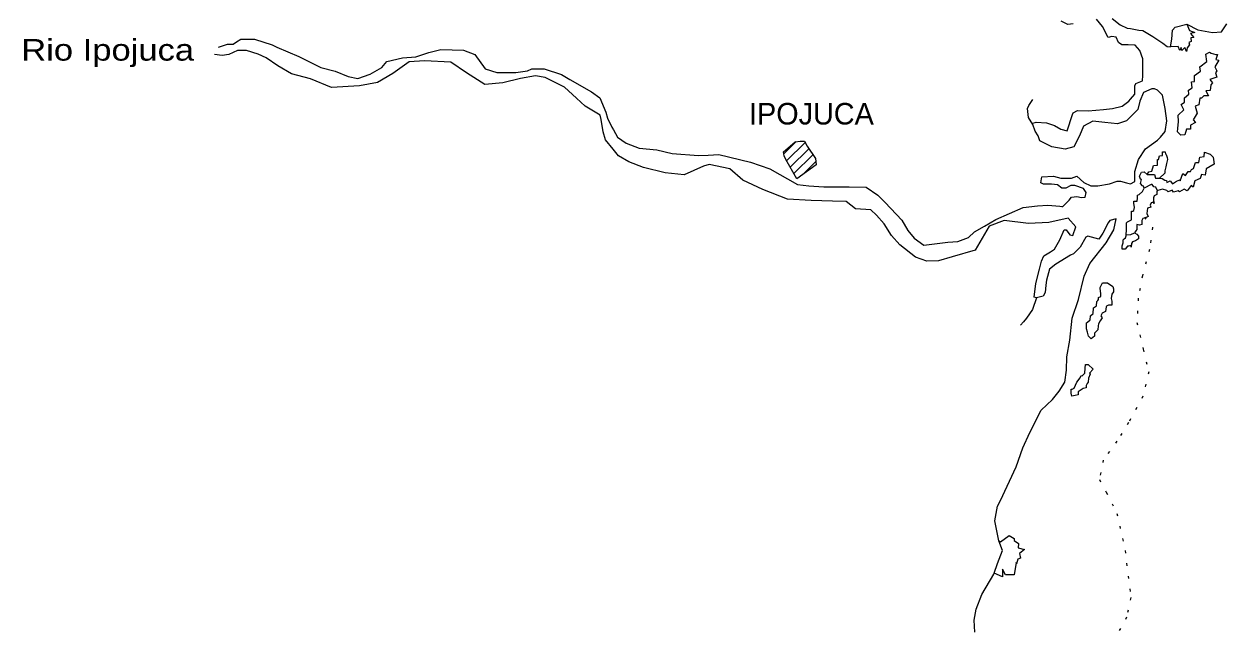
# Model space of a CAD drawing. Extents: x 47169 to 972804, y 7447977 to 9608469.
# Drawn here: x 909327 to 947160, y 9054600 to 9073613 of the extents above; entities that cross this region are included whole.
import ezdxf
from ezdxf.enums import TextEntityAlignment as Align

# ---------------------------------------------------------------- set-up
doc = ezdxf.new("R2010")
doc.units = 0
doc.header["$LTSCALE"] = 270
doc.linetypes.add('DOTTED', pattern=[1.5, 0.3, -1.2])
doc.layers.add('1', color=7, linetype='Continuous', lineweight=13)
doc.layers.add('3', color=7, linetype='Continuous')

msp = doc.modelspace()

# ---------------------------------------------------------------- linework, layer by layer
at = {"layer": '1'}
for p, q in [((933223.9, 9069536.3), (933612.8, 9069919.2)), ((933311, 9069311.6), (933895, 9069886.4)), ((933422.6, 9069111), (934012.3, 9069691.3)), ((933534.3, 9068911.5), (934138.4, 9069505)), ((933824.3, 9068886.4), (934232.2, 9069287.9))]:
    msp.add_line(p, q, dxfattribs=at)
for points in [[(941002.4, 9070544.8), (941018.4, 9070488.1), (941162.3, 9070528.7), (941488.8, 9070512.1), (941736.3, 9070423.1), (941934.9, 9070310.2), (942134.1, 9070261.7), (942303.8, 9070767.5), (942319.8, 9070822.8), (942462.9, 9070895.6), (942790.6, 9070886.7), (943276.7, 9070926), (943556.2, 9070957.5), (943859.5, 9071037.5), (944075.2, 9071189.3), (944131, 9071253.1), (944267.3, 9071413.5), (944267.2, 9071509.9), (944267.7, 9071670.6), (944299.4, 9071742.3), (944507.8, 9071831.1), (944516.1, 9071999.4), (944516.1, 9072103.6), (944509.3, 9072521.5), (944421.6, 9072786.2), (944270.9, 9072947.3), (944054.7, 9072964), (943856, 9072963.8), (943751.9, 9073036.9), (943673, 9073197.3), (943537.5, 9073222), (943425.7, 9073189.8), (943250.4, 9073535.2), (943059.6, 9073768.8)], [(942325.2, 9073625.6), (942158.3, 9073601.8), (941950.8, 9073705.9)], [(943554.3, 9073791.5), (943801.8, 9073590.5), (944024.8, 9073485.2), (944128.3, 9073469.7), (944391.7, 9073420.5), (944518.5, 9073412.5), (944830, 9073218.7), (945147.9, 9073009.3), (945275, 9072912.6), (945387.4, 9072897.1), (945427.4, 9073137.2), (945452.4, 9073418.4), (945531.7, 9073515.2), (945899.2, 9073610), (946241.8, 9073433.6), (946704.5, 9073352.3), (946991.7, 9073367.1), (947159.8, 9073615.9)], [(945899.2, 9073610), (945986.5, 9073409.6), (946145.9, 9073344.8), (946018.7, 9073312.9), (946113.4, 9073192.2), (946026.2, 9073184.2), (946033.8, 9073064.4), (945961.7, 9073031.9), (945985.2, 9072959.6), (945905.9, 9072864), (945889.2, 9072751.2), (945834.3, 9072880.3), (945746.1, 9072783.7), (945721.6, 9072872.6), (945682.1, 9072784.3), (945627, 9072904.6), (945387.4, 9072897.1)], [(928346, 9069286.9), (928021.2, 9069466.3), (927855.6, 9069684.1), (927610.2, 9069974.6), (927540.9, 9070223.5), (927473, 9070608.7), (927442.3, 9070745.3), (926974, 9071030.3), (926703.9, 9071281.2), (926324.4, 9071629.5), (925720.4, 9071932.5), (925408.6, 9071984.3), (924936.6, 9071901.4), (924384.7, 9071770.5), (923816.9, 9071712.9), (923237.8, 9072079.8), (922745.7, 9072420.3), (921922.8, 9072453.8), (921435.9, 9072426.5), (920921.4, 9072055.8), (920439.8, 9071781.3), (919879.3, 9071667.1), (918992.8, 9071620.3), (918339.9, 9071891.4), (917734.6, 9072050.2), (917313.3, 9072302.4), (916940.6, 9072555.3), (916685.7, 9072669.7), (916327.1, 9072785), (916040.1, 9072781.1), (915767.5, 9072655.2), (915559.8, 9072626.2), (915320.6, 9072651.8)], [(915437.6, 9072888.9), (915724.2, 9072977), (915899.7, 9072976.4), (916004.2, 9073056.3), (916147.3, 9073136.9), (916577.6, 9073136.1), (917127.6, 9072959), (917279.2, 9072886.7), (917972.6, 9072588.6), (918657.9, 9072250.7), (919112.5, 9072137.7), (919519.1, 9071959.8), (919829.7, 9071903.6), (920212.8, 9072039.5), (920580.1, 9072247.5), (920732, 9072432.2), (921234.1, 9072551.4), (921649.3, 9072583.9), (922056.7, 9072719.6), (922439.5, 9072815.6), (923148.8, 9072789.8), (923507.2, 9072653.3), (923826.1, 9072202.6), (924192.5, 9072090.4), (924790.6, 9072089), (925157.5, 9072145.2), (925292.8, 9072209.2), (925684.5, 9072208.7), (926225.7, 9072030.5), (926496.7, 9071869.4), (927173.8, 9071483.7), (927436.7, 9071290.6), (927627.7, 9070848.7), (927675.4, 9070655.5), (927810.5, 9070367.1), (927866, 9070286.8), (927992.8, 9070052.8), (928263.5, 9069868.4), (928670.3, 9069714.8), (929228.1, 9069658.2), (929707, 9069544.9), (930536.2, 9069479), (930847.4, 9069487), (931182.1, 9069510.2), (932178.3, 9069267.6), (932784.3, 9069057.6), (933652.3, 9068574.6), (934011.6, 9068526.6), (934481.3, 9068493.1), (934633.6, 9068492.6), (934888.6, 9068492.3), (935279.2, 9068491.7), (935813.2, 9068483), (936180.4, 9068233.2), (936411, 9068008.1), (936936.1, 9067445.4), (937119.3, 9067123.2), (937317.7, 9066882.9), (937627.8, 9066664.8), (938378.1, 9066760.2), (938697.2, 9066783.6), (939032.8, 9066903.2), (939216.8, 9067087.5), (939535.3, 9067263.8), (939887.3, 9067471.8), (940749.7, 9067847.6), (941203.8, 9067895), (941523, 9067918.4), (941905.6, 9067885.6), (941961.8, 9067877.3), (942001.6, 9067876.9), (942201.2, 9068077.7), (942266.1, 9068173.4), (942440.8, 9068197.1), (942585, 9068164.6), (942696.6, 9068173.4), (942729, 9068317.2), (942648.6, 9068445.4), (942378, 9068534.7), (942250, 9068534.9), (942090.2, 9068455.6), (941963.3, 9068455.8), (941835.3, 9068560.2), (941636.9, 9068584.4), (941389.7, 9068584.7), (941301.8, 9068625.5), (941333.5, 9068810.2), (941701.2, 9068833.1), (941932.3, 9068768.6), (942155.3, 9068768.6), (942274.5, 9068767.3), (942442.9, 9068832.1), (942657.2, 9068638.2), (942880.1, 9068526.2), (943104.1, 9068525), (943463.5, 9068588.9), (943710.5, 9068677.2), (943814.2, 9068676.2), (943998, 9068627.7), (944124.6, 9068595.4), (944261.1, 9068667.1)], [(944261.1, 9068667.1), (944261, 9068980.8), (944381.9, 9069357.5), (944598.3, 9069686.6), (944973.1, 9069966.5), (945070.1, 9070055.3), (945213.2, 9070240), (945270.7, 9070568.6), (945215.2, 9070962.6), (945129, 9071380.2), (944977.2, 9071540.3), (944881.5, 9071573.4), (944794.4, 9071581), (944538.2, 9071461.7), (944418.4, 9071188), (944353.9, 9070923.8), (944001.5, 9070570.6), (943714.6, 9070474.9), (943323.2, 9070516.6), (942940.7, 9070557.1), (942653.2, 9070404.8), (942525.4, 9070100.3), (942348.6, 9069755.2), (942069.7, 9069676), (941655.4, 9069749), (941279.9, 9069942.3), (941217.6, 9070102.6), (941129.6, 9070247.5), (941057.8, 9070456.6), (941002.4, 9070544.8), (940923.2, 9070673), (940891.9, 9070962.6), (940931.5, 9071058.6), (941051.5, 9071243.6)], [(944651.8, 9068883.7), (944707.9, 9068971.8), (944796.4, 9068987.5), (944852.3, 9069164.2), (944971.7, 9069179.6), (944980.1, 9069356.8), (945012.1, 9069356.5), (945036.4, 9069469.3), (945132.6, 9069485), (945132.7, 9069596.9), (945219.9, 9069597.1), (945228, 9069532.7), (945252.1, 9069509.2), (945283.2, 9069420.2), (945291.3, 9069355.9), (945259.2, 9069235.4), (945242.6, 9069123.6), (945210.3, 9068995.4), (945203.1, 9068931.2), (945034.8, 9068770)], [(939229.8, 9054502), (939209.4, 9054871.2), (939269.3, 9055221.9), (939449.5, 9055684.4), (939823.5, 9056321.1), (939839.2, 9056353.1), (939938.4, 9056655.8), (940102.6, 9057069.7), (939985.4, 9057367.9), (939863.9, 9057993.1), (939940.4, 9058456.7), (940038.3, 9058639.6), (940528, 9059690.8), (940741.7, 9060297), (940961.8, 9060774.6), (941312.2, 9061474.8), (941675.4, 9061814.6), (941885.6, 9062076.2), (942056.2, 9062354.8), (942115.3, 9062738.8), (942119.6, 9063154.3), (942221, 9063673.1), (942292.1, 9064369.5), (942489.1, 9064959.3), (942672.2, 9065693.3), (942851.7, 9066091.5), (943361.6, 9066734.7), (943597.6, 9067147.8), (943680.6, 9067491.7), (943480.3, 9067437.2), (943424.4, 9067365.7), (943261, 9067039.3), (943131, 9066849), (942788.7, 9066941.1), (942716.7, 9066909.8), (942545.7, 9066600.1), (942336.1, 9066386.1), (942239.7, 9066347.2), (941773.2, 9066063.8), (941580.8, 9065914), (941488.9, 9065562.5), (941463.1, 9065410.9), (941445.2, 9065179.5), (941380, 9065059.3), (941172, 9065006.1), (941092.8, 9065031.3), (941144.6, 9065455.2), (941260.7, 9065909.5), (941327.3, 9066164.8), (941400.8, 9066332.6), (941609.5, 9066450.1), (941738.4, 9066536.3), (941901.4, 9066830.6), (942040.3, 9067141.7), (942104.4, 9067148.8), (942214.2, 9066988.1), (942317.8, 9066970.4), (942408.9, 9067241), (942171, 9067508.3), (941554.9, 9067371.6), (940915.7, 9067346.1), (940157.4, 9067442.5), (939684.2, 9067256.7), (939238.5, 9066508.7), (938516.9, 9066301.1), (938084, 9066169.2), (937716.4, 9066157.4), (937366.9, 9066289.5), (936867.5, 9066671.4), (936606.8, 9066970), (936378.8, 9067333.5), (936133.2, 9067607.5), (935959.4, 9067770), (935473.1, 9067807.1), (935179.7, 9068035), (934756.1, 9068047), (934077.6, 9068071.6), (933343.1, 9068111.1), (932563.7, 9068415.9), (931935.5, 9068711.5), (931523, 9069060.2), (930869.9, 9069195.3), (930692.9, 9069149.4), (930083.2, 9068875.2), (929493.5, 9068937.6), (928807.7, 9069106.2), (928346, 9069286.9)], [(944986.6, 9068377), (944954.3, 9068353), (944953.3, 9068256.6), (944873.4, 9068216.4), (944849.6, 9068152.3), (944849.8, 9068064.8), (944873.1, 9067968.1), (944841.6, 9068016.1), (944777.3, 9067992.4), (944745.6, 9067919.6), (944761.5, 9067856.2), (944657.5, 9067824.1), (944641.5, 9067663.5), (944681.3, 9067566.7), (944577, 9067511.2), (944512.9, 9067503), (944481.3, 9067439.1), (944481.1, 9067310.5), (944409.1, 9067286.9), (944321.1, 9067311), (944321.7, 9067158.1), (944289.3, 9067117.4), (944256.6, 9067053.5), (944321.2, 9067005.2), (944376.9, 9066949.2), (944376, 9066860.5), (944280.5, 9066797.2), (944184.2, 9066772.7), (944160.4, 9066716.4), (944152.7, 9066604.6), (944136.6, 9066652.4), (944064.6, 9066628.8), (944032.6, 9066629.1), (943961.1, 9066540.1), (943865.1, 9066541), (943865, 9066637.5), (943881.1, 9066701.6), (943897.9, 9066733.5), (943897.8, 9066830), (943930.2, 9066861.8), (943969.1, 9066893.5), (943994.1, 9066957.5), (943993.3, 9066989.7), (944136.8, 9066998.2), (944256.6, 9067053.5)], [(943993.3, 9066989.7), (943993.8, 9067038.5), (944002.1, 9067094.9), (944002.3, 9067223.5), (944002.7, 9067367.5), (944035, 9067399.3), (944154.8, 9067455.7), (944154.9, 9067575.4), (944155.4, 9067728.4), (944202.9, 9067727.9), (944235.1, 9067751.9), (944250.5, 9067848.2), (944235.3, 9067984.7), (944236, 9068049), (944307.7, 9068049.3), (944338.6, 9068049), (944347.3, 9068145.3), (944347.2, 9068234), (944403.7, 9068257.8), (944499.6, 9068354.3), (944555.8, 9068458)], [(941172, 9065006.1), (941045.8, 9064643.9), (940853.2, 9064371), (940757, 9064250.1), (940669.9, 9064146.8)], [(939985.4, 9057367.9), (940032.5, 9057335.3), (940314.9, 9057539.6), (940472.8, 9057441.5), (940472.1, 9057378.4), (940606.8, 9057280.6), (940590, 9057152.2), (940796.9, 9057094.6), (940635.7, 9056975.5), (940666.1, 9056823.3), (940578.6, 9056792.1), (940545.1, 9056648.4), (940529, 9056688.4), (940469.8, 9056305.6), (940198.4, 9056300.6), (940104.2, 9056477.8), (940101.7, 9056237.3), (939839.2, 9056353.1)]]:
    msp.add_lwpolyline(points, dxfattribs=at)
for points in [[(946814.4, 9072660.7), (946863, 9072661.3), (946806.1, 9072500.1), (946901.9, 9072475.8), (946781.6, 9072267.6), (946845.5, 9072147.2), (946805.1, 9072083.4), (946836.8, 9071946.7), (946620.8, 9071866.9), (946709.2, 9071769.6), (946653.2, 9071698.1), (946628.2, 9071521), (946492.4, 9071513.6), (946580.1, 9071353.1), (946428.9, 9071353.5), (946364.2, 9071288.8), (946309, 9071281.6), (946275.9, 9071072.5), (946165.1, 9071032.6), (946228, 9070815.8), (946092.3, 9070606.7), (946172, 9070518.3), (946012.1, 9070430.2), (946012, 9070310.5), (945891.7, 9070310.6), (945835.8, 9070133.8), (945707.6, 9070118.5), (945604.9, 9070222.7), (945620.4, 9070335.6), (945637, 9070551.5), (945629.1, 9070752.2), (945805.2, 9070913.3), (945717.6, 9071089.3), (945829.8, 9071161.3), (945830.1, 9071297.6), (945965.9, 9071410.4), (945950.7, 9071539.1), (946070.7, 9071611), (946047.2, 9071795.2), (946134.5, 9071803.2), (946135.3, 9071996.1), (946326.6, 9072132.6), (946311.4, 9072269.1), (946527.3, 9072436.5), (946495.5, 9072669.6), (946615.4, 9072733.7), (946663.6, 9072701.1)], [(933628.6, 9068743.2), (933287.1, 9069354), (933232.1, 9069475.3), (933215.6, 9069595.1), (933583, 9069916.1), (933735.5, 9069931.2), (933871.2, 9069931), (933957.9, 9069770.5), (934220, 9069384.5), (934244.5, 9069192.5)], [(944555.8, 9068458), (944532.2, 9068514.7), (944500.3, 9068530.6), (944443.7, 9068603.2), (944468.1, 9068723.7), (944444, 9068739.5), (944405.1, 9068827.5), (944469.4, 9068956.5), (944556.7, 9068964.4), (944651.8, 9068883.7), (944883.6, 9068883.5), (944915.6, 9068771.2), (945034.8, 9068770), (945122.9, 9068754.7), (945201.8, 9068706.2), (945258.1, 9068697.9), (945266.2, 9068633.5), (945377.2, 9068690), (945449, 9068592.8), (945576.8, 9068673.5), (945673.3, 9068721.3), (945688.4, 9068689), (945769.1, 9068913.1), (945856.8, 9068856.8), (945944.1, 9068977.8), (946015.9, 9068977.1), (946040.8, 9069041.1), (946104.1, 9069073.7), (946169, 9069265.9), (946272.7, 9069265.9), (946304.2, 9069434.1), (946447.9, 9069450.3), (946457, 9069586.5), (946631.9, 9069521.6), (946727, 9069433), (946758.8, 9069208.8), (946511.2, 9069065.1), (946478.2, 9068863.7), (946359.2, 9068880.4), (946319.3, 9068760), (946150.8, 9068687.5), (946094.7, 9068487.5), (946038.9, 9068535.7), (945911.4, 9068375.2), (945815.9, 9068423.9), (945663.9, 9068343.4), (945624.5, 9068376), (945480.5, 9068327.6), (945440.3, 9068392.3), (945312.9, 9068344.8), (945264.8, 9068384.1), (945137.1, 9068425.3), (944986.6, 9068377), (944970.2, 9068392.7), (944922.6, 9068489.6), (944858.7, 9068498.1), (944810.8, 9068570.6), (944778.8, 9068569.8)], [(943567.1, 9065361.6), (943590.6, 9065289.3), (943591, 9065225), (943590.7, 9065192.8), (943542.6, 9065128), (943519.1, 9064991.9), (943542.4, 9064903), (943542.2, 9064775.5), (943430.8, 9064775.6), (943366.5, 9064750.7), (943366.3, 9064727.5), (943342.6, 9064574.8), (943230.7, 9064527.2), (943197.8, 9064438.8), (943230.2, 9064374.2), (943174.1, 9064286.1), (943117.9, 9064189.2), (943109.5, 9064125), (943093.9, 9063996.6), (942997.9, 9063893.4), (942997, 9063804.7), (942893.4, 9063716), (942806.1, 9063804.5), (942774.3, 9063933.4), (942743.3, 9064030.1), (942743.1, 9064223), (942775.2, 9064238.1), (942855.5, 9064318.2), (942863.5, 9064446.7), (942951.4, 9064518.9), (942967.6, 9064696.1), (943055.3, 9064751.7), (943072.2, 9064887.9), (943095.7, 9064920.9), (943119.2, 9064952.8), (943119.9, 9065017.1), (943191.9, 9065048.5), (943191.8, 9065144.9), (943176.8, 9065298), (943176.1, 9065330.1), (943248.2, 9065474.6), (943400.5, 9065474.1)], [(942483.4, 9062055.6), (942482.4, 9061959.2), (942387.3, 9061934.7), (942283.4, 9061919.1), (942260.1, 9062015.8), (942260.3, 9062135.5), (942292.3, 9062136.3), (942355.5, 9062167.8), (942443.6, 9062360.8), (942547.5, 9062488.3), (942571.4, 9062561.2), (942603.4, 9062560.8), (942691.4, 9062640.8), (942699.6, 9062793.7), (942716.3, 9062914.3), (942795.8, 9062913.5), (942947.7, 9062769), (942834.9, 9062640.5), (942858.8, 9062608.1), (942803.4, 9062480.1), (942794.5, 9062359.4), (942763.1, 9062319.8), (942730.4, 9062247), (942730.8, 9062182.7), (942634.6, 9062159.3)]]:
    msp.add_lwpolyline(points, close=True, dxfattribs=at)
at = {"layer": '1', "linetype": 'DOTTED'}
msp.add_lwpolyline([(944561.8, 9067542.4), (944823.4, 9067221.6), (944726.9, 9066531), (944500.9, 9065704.3), (944372.2, 9064998.6), (944330.1, 9064235.4), (944527.7, 9063392.1), (944701.4, 9062685.4), (944516.8, 9061914.8), (944067.9, 9061088.3), (943699.9, 9060503.6), (943267.8, 9059909.6), (943146.7, 9059292.4), (943361.1, 9058897.8), (943701.7, 9058230.4), (943954.4, 9057066.2), (944134.2, 9055588.1), (944005.3, 9054971), (943148.7, 9053447.1)], dxfattribs=at)

# ---------------------------------------------------------------- texts
at = {"layer": '3', "width": 1.2}
msp.add_text('Rio Ipojuca', height=677.2, dxfattribs=at).set_placement((914674.1, 9072464.2), align=Align.RIGHT)
at = {"layer": '3'}
msp.add_text('IPOJUCA', height=677.3, dxfattribs=at).set_placement((936053.5, 9070456), align=Align.RIGHT)

doc.saveas('drawing.dxf')
